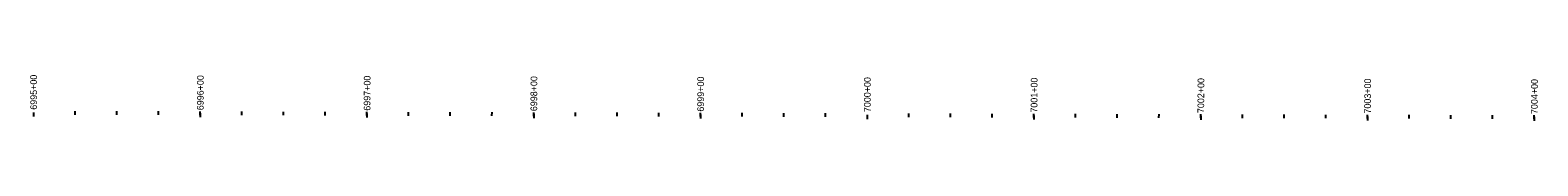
# Model space of a CAD drawing. Extents: x 5195296 to 5198948, y 3709168 to 3709552.
# Drawn here: x 5195296 to 5196200, y 3709352 to 3709380 of the extents above; entities that cross this region are included whole.
import ezdxf

# ---------------------------------------------------------------- set-up
doc = ezdxf.new("R2010")
doc.units = 0
doc.layers.add('dsnAlignmentStation', color=7, linetype='Continuous')
doc.layers.add('dsnProfileEntranceGradeProp', color=7, linetype='Continuous')

msp = doc.modelspace()

# ---------------------------------------------------------------- linework, layer by layer
at = {"layer": 'dsnAlignmentStation'}
for p, q in [((5195297.85, 3709357.15), (5195297.84, 3709354.7)), ((5195322.84, 3709355.85), (5195322.85, 3709358.03)), ((5195347.84, 3709355.78), (5195347.85, 3709357.96)), ((5195372.84, 3709355.71), (5195372.85, 3709357.89)), ((5195397.85, 3709356.86), (5195397.84, 3709354.41)), ((5195422.84, 3709355.56), (5195422.85, 3709357.75)), ((5195447.84, 3709355.49), (5195447.85, 3709357.67)), ((5195472.84, 3709355.42), (5195472.85, 3709357.6)), ((5195497.85, 3709356.57), (5195497.84, 3709354.12)), ((5195522.84, 3709355.27), (5195522.85, 3709357.46)), ((5195547.84, 3709355.2), (5195547.85, 3709357.38)), ((5195572.84, 3709355.13), (5195572.85, 3709357.31)), ((5195597.85, 3709356.28), (5195597.84, 3709353.83)), ((5195622.84, 3709354.98), (5195622.85, 3709357.17)), ((5195647.84, 3709354.91), (5195647.85, 3709357.1)), ((5195672.84, 3709354.84), (5195672.85, 3709357.02)), ((5195722.84, 3709354.69), (5195722.85, 3709356.88)), ((5195747.84, 3709354.62), (5195747.85, 3709356.81)), ((5195772.84, 3709354.55), (5195772.85, 3709356.73)), ((5195822.84, 3709354.41), (5195822.85, 3709356.59)), ((5195847.84, 3709354.33), (5195847.85, 3709356.52)), ((5195872.84, 3709354.26), (5195872.85, 3709356.45)), ((5195922.84, 3709354.12), (5195922.85, 3709356.3)), ((5195947.84, 3709354.04), (5195947.85, 3709356.23)), ((5195697.85, 3709355.99), (5195697.84, 3709353.54)), ((5195797.84, 3709355.7), (5195797.84, 3709353.25)), ((5195897.84, 3709355.41), (5195897.84, 3709352.97)), ((5195972.84, 3709353.97), (5195972.85, 3709356.16)), ((5195997.84, 3709355.12), (5195997.84, 3709352.68)), ((5196022.84, 3709353.83), (5196022.85, 3709356.01)), ((5196047.84, 3709353.76), (5196047.85, 3709355.94)), ((5196072.84, 3709353.68), (5196072.85, 3709355.87)), ((5196097.84, 3709354.84), (5196097.84, 3709352.39)), ((5196122.84, 3709353.54), (5196122.85, 3709355.72)), ((5196147.84, 3709353.47), (5196147.85, 3709355.65)), ((5196172.84, 3709353.39), (5196172.85, 3709355.58)), ((5196197.84, 3709354.55), (5196197.84, 3709352.1))]:
    msp.add_line(p, q, dxfattribs=at)
at = {"layer": 'dsnProfileEntranceGradeProp'}
for p, q in [((5195297.85, 3709357.15), (5195297.84, 3709354.7)), ((5195397.84, 3709355.63), (5195397.85, 3709357.82)), ((5195497.84, 3709355.34), (5195497.85, 3709357.53)), ((5195597.84, 3709355.06), (5195597.85, 3709357.24)), ((5195697.84, 3709354.77), (5195697.85, 3709356.95)), ((5195897.84, 3709354.19), (5195897.85, 3709356.37)), ((5195797.84, 3709355.7), (5195797.84, 3709353.25)), ((5195997.84, 3709353.9), (5195997.85, 3709356.08)), ((5196097.84, 3709353.61), (5196097.85, 3709355.8)), ((5196197.84, 3709353.32), (5196197.85, 3709355.51))]:
    msp.add_line(p, q, dxfattribs=at)

# ---------------------------------------------------------------- texts
at = {"layer": 'dsnAlignmentStation'}
for s, p in [('6995+00', (5195299.93, 3709358.83)), ('6996+00', (5195399.93, 3709358.54)), ('6997+00', (5195499.93, 3709358.25)), ('6998+00', (5195599.93, 3709357.96)), ('6999+00', (5195699.93, 3709357.67)), ('7000+00', (5195799.93, 3709357.38)), ('7001+00', (5195899.93, 3709357.09)), ('7002+00', (5195999.93, 3709356.81)), ('7003+00', (5196099.93, 3709356.52)), ('7004+00', (5196199.93, 3709356.23))]:
    msp.add_text(s, height=4.008, rotation=89.83445, dxfattribs=at).set_placement(p)
at = {"layer": 'dsnProfileEntranceGradeProp'}
for s, p in [('6995+00', (5195299.93, 3709358.83)), ('7000+00', (5195799.93, 3709357.38))]:
    msp.add_text(s, height=4.008, rotation=89.83445, dxfattribs=at).set_placement(p)

doc.saveas('drawing.dxf')
